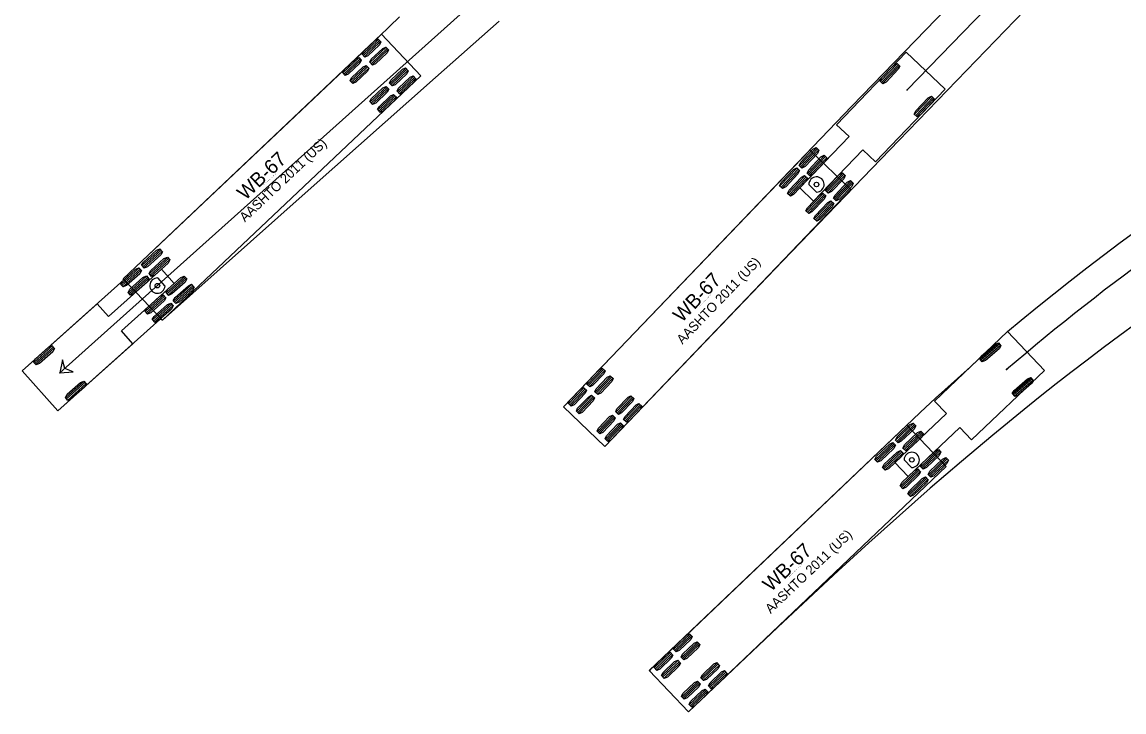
# Model space of a CAD drawing. Extents: x 2175591 to 2194071, y 76570 to 86955.
# Drawn here: x 2176278.8 to 2176443, y 77091.2 to 77193.9 of the extents above; entities that cross this region are included whole.
import ezdxf

# ---------------------------------------------------------------- set-up
doc = ezdxf.new("R2010")
doc.units = 0
doc.layers.add('C-UTIL-STRM-TEXT', color=7, linetype='Continuous')

msp = doc.modelspace()

# ---------------------------------------------------------------- linework, layer by layer
at = {"layer": 'C-UTIL-STRM-TEXT'}
for p, q in [((2176410.68, 77183.82), (2176502.54, 77278.59)), ((2176348.69, 77199.2), (2176284.46, 77141.66)), ((2176332.37, 77192.12), (2176293.88, 77155.69)), ((2176329.52, 77189.11), (2176331.91, 77191.37)), ((2176329.67, 77188.94), (2176332.07, 77191.21)), ((2176329.83, 77188.77), (2176332.23, 77191.04)), ((2176338.22, 77185.95), (2176332.37, 77192.12)), ((2176330.65, 77187.91), (2176333.05, 77190.18)), ((2176330.81, 77187.74), (2176333.21, 77190.01)), ((2176330.97, 77187.57), (2176333.36, 77189.84)), ((2176410.56, 77189.47), (2176400.18, 77178.65)), ((2176416.33, 77183.93), (2176410.56, 77189.47)), ((2176410.56, 77189.47), (2176410.56, 77189.47)), ((2176326.61, 77186.36), (2176329.01, 77188.62)), ((2176326.77, 77186.19), (2176329.17, 77188.46)), ((2176326.93, 77186.02), (2176329.32, 77188.29)), ((2176327.75, 77185.16), (2176330.14, 77187.43)), ((2176327.9, 77184.99), (2176330.3, 77187.26)), ((2176409.23, 77187.75), (2176406.69, 77185.1)), ((2176409.39, 77187.59), (2176406.85, 77184.94)), ((2176409.56, 77187.43), (2176407.02, 77184.79)), ((2176299.73, 77149.52), (2176338.22, 77185.95)), ((2176328.06, 77184.82), (2176330.46, 77187.09)), ((2176333.6, 77184.8), (2176335.99, 77187.06)), ((2176333.75, 77184.63), (2176336.15, 77186.9)), ((2176333.91, 77184.46), (2176336.31, 77186.73)), ((2176334.73, 77183.6), (2176337.13, 77185.87)), ((2176334.89, 77183.43), (2176337.28, 77185.7)), ((2176330.69, 77182.05), (2176333.09, 77184.31)), ((2176330.85, 77181.88), (2176333.24, 77184.15)), ((2176331.01, 77181.71), (2176333.4, 77183.98)), ((2176335.05, 77183.26), (2176337.44, 77185.53)), ((2176331.83, 77180.85), (2176334.22, 77183.12)), ((2176331.98, 77180.68), (2176334.38, 77182.95)), ((2176332.14, 77180.52), (2176334.54, 77182.78)), ((2176405.95, 77173.11), (2176416.33, 77183.93)), ((2176414.34, 77182.84), (2176411.8, 77180.2)), ((2176414.5, 77182.69), (2176411.96, 77180.04)), ((2176414.67, 77182.53), (2176412.13, 77179.88)), ((2176400.18, 77178.65), (2176402.03, 77176.87)), ((2176402.03, 77176.87), (2176394.69, 77169.22)), ((2176396.19, 77174.85), (2176359.5, 77136.61)), ((2176397.18, 77175.19), (2176394.64, 77172.55)), ((2176397.35, 77175.03), (2176394.81, 77172.39)), ((2176397.51, 77174.88), (2176394.97, 77172.23)), ((2176402.32, 77168.97), (2176396.19, 77174.85)), ((2176396.19, 77174.85), (2176396.19, 77174.85)), ((2176396.76, 77167.24), (2176404.1, 77174.89)), ((2176404.1, 77174.89), (2176405.95, 77173.11)), ((2176398.37, 77174.05), (2176395.83, 77171.4)), ((2176398.54, 77173.89), (2176396, 77171.25)), ((2176398.7, 77173.73), (2176396.16, 77171.09)), ((2176394.27, 77172.16), (2176391.73, 77169.52)), ((2176394.44, 77172), (2176391.9, 77169.36)), ((2176394.6, 77171.84), (2176392.06, 77169.2)), ((2176395.46, 77171.02), (2176392.92, 77168.37)), ((2176395.63, 77170.86), (2176393.09, 77168.22)), ((2176401.1, 77171.43), (2176398.56, 77168.79)), ((2176401.27, 77171.27), (2176398.73, 77168.63)), ((2176401.43, 77171.11), (2176398.89, 77168.47)), ((2176395.79, 77170.7), (2176393.25, 77168.06)), ((2176394.69, 77169.22), (2176396.76, 77167.24)), ((2176396.04, 77169.72), (2176397.2, 77168.6)), ((2176402.29, 77170.29), (2176399.75, 77167.64)), ((2176402.46, 77170.13), (2176399.92, 77167.48)), ((2176402.62, 77169.97), (2176400.08, 77167.33)), ((2176365.63, 77130.72), (2176402.32, 77168.97)), ((2176398.19, 77168.4), (2176395.65, 77165.75)), ((2176398.36, 77168.24), (2176395.82, 77165.6)), ((2176398.52, 77168.08), (2176395.99, 77165.44)), ((2176399.38, 77167.26), (2176396.84, 77164.61)), ((2176399.55, 77167.1), (2176397.01, 77164.45)), ((2176399.71, 77166.94), (2176397.18, 77164.29)), ((2176296.67, 77157.65), (2176299.4, 77160.1)), ((2176296.82, 77157.48), (2176299.55, 77159.93)), ((2176296.97, 77157.31), (2176299.7, 77159.76)), ((2176297.77, 77156.42), (2176300.5, 77158.87)), ((2176297.92, 77156.25), (2176300.65, 77158.7)), ((2176298.07, 77156.08), (2176300.8, 77158.53)), ((2176299.59, 77157.14), (2176291.69, 77150.06)), ((2176293.54, 77154.85), (2176296.27, 77157.3)), ((2176293.69, 77154.68), (2176296.42, 77157.13)), ((2176293.84, 77154.51), (2176296.57, 77156.96)), ((2176294.64, 77153.62), (2176297.37, 77156.07)), ((2176301.5, 77155), (2176299.59, 77157.14)), ((2176300.29, 77153.61), (2176303.02, 77156.05)), ((2176293.61, 77147.93), (2176301.5, 77155)), ((2176293.88, 77155.69), (2176299.73, 77149.52)), ((2176294.79, 77153.45), (2176297.52, 77155.9)), ((2176294.94, 77153.28), (2176297.67, 77155.73)), ((2176300.12, 77154.6), (2176299.05, 77155.81)), ((2176300.44, 77153.44), (2176303.17, 77155.88)), ((2176300.6, 77153.26), (2176303.33, 77155.71)), ((2176301.39, 77152.38), (2176304.12, 77154.82)), ((2176301.54, 77152.21), (2176304.28, 77154.65)), ((2176301.7, 77152.04), (2176304.43, 77154.48)), ((2176297.16, 77150.8), (2176299.89, 77153.25)), ((2176297.31, 77150.63), (2176300.05, 77153.08)), ((2176297.47, 77150.46), (2176300.2, 77152.91)), ((2176289.98, 77151.97), (2176278.81, 77141.97)), ((2176291.69, 77150.06), (2176289.98, 77151.97)), ((2176298.26, 77149.57), (2176300.99, 77152.02)), ((2176298.42, 77149.4), (2176301.15, 77151.85)), ((2176298.57, 77149.23), (2176301.3, 77151.68)), ((2176299.73, 77149.52), (2176299.73, 77149.52)), ((2176295.32, 77146.02), (2176293.61, 77147.93)), ((2176425.64, 77147.82), (2176414.78, 77137.47)), ((2176431.16, 77142.02), (2176425.64, 77147.82)), ((2176425.64, 77147.82), (2176425.64, 77147.82)), ((2176280.58, 77143.24), (2176283.31, 77145.69)), ((2176280.73, 77143.07), (2176283.46, 77145.52)), ((2176280.88, 77142.9), (2176283.61, 77145.35)), ((2176284.15, 77136.01), (2176295.32, 77146.02)), ((2176424.32, 77146.11), (2176421.53, 77143.72)), ((2176424.47, 77145.93), (2176421.68, 77143.55)), ((2176424.62, 77145.76), (2176421.83, 77143.38)), ((2176278.81, 77141.97), (2176284.15, 77136.01)), ((2176365.3, 77142.33), (2176363.02, 77139.95)), ((2176365.47, 77142.17), (2176363.18, 77139.79)), ((2176365.63, 77142.01), (2176363.35, 77139.63)), ((2176420.29, 77131.68), (2176431.16, 77142.02)), ((2176285.3, 77137.97), (2176288.03, 77140.41)), ((2176285.45, 77137.79), (2176288.19, 77140.24)), ((2176285.61, 77137.62), (2176288.34, 77140.07)), ((2176366.49, 77141.19), (2176364.21, 77138.8)), ((2176366.66, 77141.03), (2176364.37, 77138.65)), ((2176366.82, 77140.87), (2176364.54, 77138.49)), ((2176429.17, 77140.94), (2176426.38, 77138.56)), ((2176429.32, 77140.77), (2176426.53, 77138.39)), ((2176429.47, 77140.59), (2176426.68, 77138.21)), ((2176362.53, 77139.44), (2176360.25, 77137.06)), ((2176362.7, 77139.28), (2176360.41, 77136.9)), ((2176362.86, 77139.12), (2176360.58, 77136.74)), ((2176363.72, 77138.3), (2176361.44, 77135.92)), ((2176363.89, 77138.14), (2176361.61, 77135.76)), ((2176364.06, 77137.98), (2176361.77, 77135.6)), ((2176369.58, 77138.22), (2176367.3, 77135.84)), ((2176369.75, 77138.06), (2176367.47, 77135.68)), ((2176359.5, 77136.61), (2176365.63, 77130.72)), ((2176369.92, 77137.9), (2176367.63, 77135.52)), ((2176370.78, 77137.08), (2176368.49, 77134.7)), ((2176370.94, 77136.92), (2176368.66, 77134.54)), ((2176371.11, 77136.76), (2176368.82, 77134.38)), ((2176414.78, 77137.47), (2176416.55, 77135.61)), ((2176284.15, 77136.01), (2176284.15, 77136.01)), ((2176366.82, 77135.33), (2176364.53, 77132.95)), ((2176366.98, 77135.18), (2176364.7, 77132.79)), ((2176367.15, 77135.02), (2176364.86, 77132.64)), ((2176416.55, 77135.61), (2176408.87, 77128.3)), ((2176368.01, 77134.19), (2176365.72, 77131.81)), ((2176368.17, 77134.03), (2176365.89, 77131.65)), ((2176368.34, 77133.87), (2176366.05, 77131.49)), ((2176410.62, 77133.86), (2176372.24, 77097.31)), ((2176411.63, 77134.16), (2176408.97, 77131.63)), ((2176411.79, 77133.99), (2176409.13, 77131.46)), ((2176411.94, 77133.82), (2176409.29, 77131.29)), ((2176416.48, 77127.7), (2176410.62, 77133.86)), ((2176410.62, 77133.86), (2176410.62, 77133.86)), ((2176410.85, 77126.23), (2176418.52, 77133.54)), ((2176418.52, 77133.54), (2176420.29, 77131.68)), ((2176412.77, 77132.96), (2176410.11, 77130.43)), ((2176412.92, 77132.79), (2176410.27, 77130.27)), ((2176413.08, 77132.63), (2176410.43, 77130.1)), ((2176408.59, 77131.26), (2176405.93, 77128.73)), ((2176408.74, 77131.09), (2176406.09, 77128.56)), ((2176408.9, 77130.93), (2176406.25, 77128.4)), ((2176409.72, 77130.06), (2176407.07, 77127.54)), ((2176409.88, 77129.9), (2176407.23, 77127.37)), ((2176415.37, 77130.22), (2176412.72, 77127.69)), ((2176415.53, 77130.05), (2176412.88, 77127.53)), ((2176415.69, 77129.89), (2176413.04, 77127.36)), ((2176410.04, 77129.73), (2176407.38, 77127.2)), ((2176408.87, 77128.3), (2176410.85, 77126.23)), ((2176410.24, 77128.74), (2176411.35, 77127.57)), ((2176416.51, 77129.03), (2176413.86, 77126.5)), ((2176416.67, 77128.86), (2176414.02, 77126.33)), ((2176416.83, 77128.69), (2176414.17, 77126.17)), ((2176378.1, 77091.15), (2176416.48, 77127.7)), ((2176412.33, 77127.32), (2176409.68, 77124.8)), ((2176412.49, 77127.16), (2176409.84, 77124.63)), ((2176412.65, 77126.99), (2176409.99, 77124.46)), ((2176413.47, 77126.13), (2176410.82, 77123.6)), ((2176413.63, 77125.96), (2176410.97, 77123.43)), ((2176413.79, 77125.8), (2176411.13, 77123.27)), ((2176378.3, 77102.76), (2176375.91, 77100.49)), ((2176378.46, 77102.6), (2176376.07, 77100.32)), ((2176378.62, 77102.43), (2176376.23, 77100.15)), ((2176379.44, 77101.57), (2176377.05, 77099.29)), ((2176379.6, 77101.4), (2176377.21, 77099.13)), ((2176379.75, 77101.24), (2176377.37, 77098.96)), ((2176375.4, 77100), (2176373.01, 77097.73)), ((2176375.56, 77099.84), (2176373.17, 77097.56)), ((2176375.72, 77099.67), (2176373.33, 77097.4)), ((2176376.54, 77098.81), (2176374.15, 77096.53)), ((2176376.7, 77098.64), (2176374.31, 77096.37)), ((2176372.24, 77097.31), (2176378.1, 77091.15)), ((2176376.86, 77098.48), (2176374.47, 77096.2)), ((2176382.39, 77098.47), (2176380, 77096.19)), ((2176382.55, 77098.3), (2176380.16, 77096.02)), ((2176382.71, 77098.13), (2176380.32, 77095.86)), ((2176383.53, 77097.27), (2176381.14, 77094.99)), ((2176383.69, 77097.1), (2176381.3, 77094.83)), ((2176383.85, 77096.94), (2176381.46, 77094.66)), ((2176379.5, 77095.71), (2176377.11, 77093.43)), ((2176379.65, 77095.54), (2176377.26, 77093.27)), ((2176379.81, 77095.37), (2176377.42, 77093.1)), ((2176380.63, 77094.51), (2176378.24, 77092.24)), ((2176380.79, 77094.35), (2176378.4, 77092.07)), ((2176380.95, 77094.18), (2176378.56, 77091.9))]:
    msp.add_line(p, q, dxfattribs=at)
for points in [[(2176508.36, 77278.86), (2176502.22, 77272.5), (2176500.11, 77270.16), (2176497.97, 77267.84), (2176495.95, 77265.7), (2176426.72, 77194.16), (2176409.45, 77176.28), (2176392.19, 77158.38), (2176365.63, 77130.72), (2176359.5, 77136.61), (2176359.7, 77136.82), (2176359.7, 77136.82)], [(2176359.7, 77136.82), (2176402.47, 77181.39), (2176419.75, 77199.27), (2176462.92, 77243.83), (2176467.17, 77248.29), (2176471.25, 77252.61), (2176473.34, 77254.87), (2176475.42, 77257.13), (2176477.47, 77259.4), (2176479.48, 77261.68), (2176481.38, 77263.88), (2176483.31, 77266.17), (2176485.19, 77268.47), (2176487.04, 77270.81), (2176488.74, 77273.02)], [(2176349.89, 77194.08), (2176340.39, 77185.68), (2176321.43, 77168.86), (2176299.73, 77149.52), (2176299.34, 77149.62), (2176284.15, 77136.01), (2176278.81, 77141.97), (2176293.96, 77155.54), (2176293.88, 77155.69), (2176330.52, 77190.37), (2176335.07, 77194.7)], [(2176372.43, 77097.49), (2176408.4, 77131.74), (2176412.64, 77135.77), (2176414.93, 77137.89), (2176417.23, 77139.99), (2176420.11, 77142.56), (2176425.64, 77147.82), (2176427.69, 77149.52), (2176430.11, 77151.5), (2176432.54, 77153.45), (2176434.99, 77155.39), (2176437.46, 77157.3), (2176439.95, 77159.2), (2176442.45, 77161.08), (2176444.97, 77162.93)], [(2176444.81, 77149.03), (2176442.36, 77147.24), (2176439.92, 77145.42), (2176437.5, 77143.59), (2176435.09, 77141.73), (2176432.91, 77140.03), (2176430.52, 77138.14), (2176428.15, 77136.23), (2176423.46, 77132.39), (2176418.78, 77128.46), (2176414.14, 77124.47), (2176409.54, 77120.42), (2176404.97, 77116.33), (2176400.43, 77112.19), (2176395.92, 77108.02), (2176391.43, 77103.81), (2176378.1, 77091.15), (2176372.24, 77097.31), (2176372.43, 77097.49), (2176372.43, 77097.49)]]:
    msp.add_lwpolyline(points, dxfattribs=at)
for points in [[(2176329.87, 77188.73), (2176329.48, 77189.15), (2176329.7, 77189.59), (2176331.42, 77191.22), (2176331.87, 77191.41), (2176332.27, 77191), (2176332.05, 77190.56), (2176330.33, 77188.92)], [(2176331.01, 77187.53), (2176330.61, 77187.95), (2176330.83, 77188.39), (2176332.55, 77190.02), (2176333.01, 77190.22), (2176333.4, 77189.8), (2176333.19, 77189.36), (2176331.46, 77187.73)], [(2176326.97, 77185.98), (2176326.57, 77186.4), (2176326.79, 77186.84), (2176328.52, 77188.47), (2176328.97, 77188.67), (2176329.36, 77188.25), (2176329.15, 77187.81), (2176327.42, 77186.17)], [(2176328.1, 77184.78), (2176327.71, 77185.2), (2176327.92, 77185.64), (2176329.65, 77187.27), (2176330.1, 77187.47), (2176330.5, 77187.05), (2176330.28, 77186.61), (2176328.55, 77184.98)], [(2176409.18, 77187.79), (2176409.6, 77187.39), (2176409.37, 77186.9), (2176407.54, 77185), (2176407.06, 77184.75), (2176406.65, 77185.14), (2176406.88, 77185.63), (2176408.71, 77187.54)], [(2176333.95, 77184.42), (2176333.56, 77184.84), (2176333.77, 77185.28), (2176335.5, 77186.91), (2176335.95, 77187.11), (2176336.35, 77186.69), (2176336.13, 77186.25), (2176334.4, 77184.61)], [(2176335.08, 77183.22), (2176334.69, 77183.64), (2176334.91, 77184.08), (2176336.63, 77185.72), (2176337.09, 77185.91), (2176337.48, 77185.49), (2176337.26, 77185.05), (2176335.54, 77183.42)], [(2176331.04, 77181.67), (2176330.65, 77182.09), (2176330.87, 77182.53), (2176332.59, 77184.16), (2176333.05, 77184.36), (2176333.44, 77183.94), (2176333.22, 77183.5), (2176331.5, 77181.86)], [(2176332.18, 77180.47), (2176331.79, 77180.89), (2176332, 77181.33), (2176333.73, 77182.97), (2176334.18, 77183.16), (2176334.58, 77182.74), (2176334.36, 77182.3), (2176332.63, 77180.67)], [(2176414.3, 77182.88), (2176414.71, 77182.49), (2176414.48, 77182), (2176412.65, 77180.09), (2176412.17, 77179.84), (2176411.76, 77180.24), (2176411.99, 77180.73), (2176413.82, 77182.63)], [(2176397.14, 77175.23), (2176397.55, 77174.84), (2176397.32, 77174.35), (2176395.49, 77172.44), (2176395.01, 77172.19), (2176394.6, 77172.59), (2176394.83, 77173.08), (2176396.66, 77174.98)], [(2176398.33, 77174.09), (2176398.74, 77173.69), (2176398.51, 77173.2), (2176396.68, 77171.3), (2176396.2, 77171.05), (2176395.79, 77171.44), (2176396.02, 77171.93), (2176397.85, 77173.84)], [(2176394.23, 77172.2), (2176394.64, 77171.81), (2176394.41, 77171.32), (2176392.59, 77169.41), (2176392.11, 77169.16), (2176391.69, 77169.56), (2176391.92, 77170.05), (2176393.75, 77171.95)], [(2176395.42, 77171.06), (2176395.83, 77170.66), (2176395.6, 77170.17), (2176393.78, 77168.27), (2176393.3, 77168.02), (2176392.88, 77168.41), (2176393.11, 77168.9), (2176394.94, 77170.81)], [(2176401.06, 77171.47), (2176401.47, 77171.07), (2176401.24, 77170.58), (2176399.41, 77168.68), (2176398.93, 77168.43), (2176398.52, 77168.82), (2176398.75, 77169.31), (2176400.58, 77171.22)], [(2176402.25, 77170.33), (2176402.66, 77169.93), (2176402.43, 77169.44), (2176400.6, 77167.54), (2176400.12, 77167.29), (2176399.71, 77167.68), (2176399.94, 77168.17), (2176401.77, 77170.08)], [(2176398.15, 77168.44), (2176398.56, 77168.04), (2176398.33, 77167.55), (2176396.51, 77165.65), (2176396.03, 77165.4), (2176395.61, 77165.79), (2176395.84, 77166.28), (2176397.67, 77168.19)], [(2176399.34, 77167.3), (2176399.76, 77166.9), (2176399.52, 77166.41), (2176397.7, 77164.51), (2176397.22, 77164.26), (2176396.8, 77164.65), (2176397.03, 77165.14), (2176398.86, 77167.05)], [(2176297.01, 77157.27), (2176296.63, 77157.7), (2176296.89, 77158.17), (2176298.86, 77159.93), (2176299.36, 77160.14), (2176299.74, 77159.72), (2176299.47, 77159.25), (2176297.51, 77157.48)], [(2176298.11, 77156.04), (2176297.73, 77156.47), (2176298, 77156.94), (2176299.96, 77158.7), (2176300.46, 77158.91), (2176300.84, 77158.49), (2176300.57, 77158.02), (2176298.61, 77156.25)], [(2176293.88, 77154.47), (2176293.5, 77154.89), (2176293.77, 77155.36), (2176295.73, 77157.13), (2176296.23, 77157.34), (2176296.61, 77156.91), (2176296.34, 77156.44), (2176294.38, 77154.68)], [(2176294.98, 77153.24), (2176294.6, 77153.66), (2176294.87, 77154.14), (2176296.83, 77155.9), (2176297.33, 77156.11), (2176297.71, 77155.68), (2176297.45, 77155.21), (2176295.48, 77153.45)], [(2176300.63, 77153.22), (2176300.25, 77153.65), (2176300.52, 77154.12), (2176302.49, 77155.88), (2176302.98, 77156.09), (2176303.37, 77155.67), (2176303.1, 77155.2), (2176301.13, 77153.44)], [(2176301.73, 77151.99), (2176301.35, 77152.42), (2176301.62, 77152.89), (2176303.59, 77154.65), (2176304.08, 77154.87), (2176304.47, 77154.44), (2176304.2, 77153.97), (2176302.23, 77152.21)], [(2176297.51, 77150.42), (2176297.12, 77150.85), (2176297.39, 77151.32), (2176299.36, 77153.08), (2176299.86, 77153.29), (2176300.24, 77152.87), (2176299.97, 77152.4), (2176298, 77150.63)], [(2176298.61, 77149.19), (2176298.22, 77149.62), (2176298.49, 77150.09), (2176300.46, 77151.85), (2176300.96, 77152.06), (2176301.34, 77151.64), (2176301.07, 77151.17), (2176299.1, 77149.41)], [(2176280.92, 77142.86), (2176280.54, 77143.28), (2176280.81, 77143.75), (2176282.77, 77145.52), (2176283.27, 77145.73), (2176283.65, 77145.3), (2176283.38, 77144.83), (2176281.42, 77143.07)], [(2176424.28, 77146.15), (2176424.66, 77145.72), (2176424.38, 77145.25), (2176422.37, 77143.53), (2176421.87, 77143.33), (2176421.5, 77143.77), (2176421.78, 77144.23), (2176423.78, 77145.95)], [(2176284.46, 77141.66), (2176286.45, 77141.81), (2176285.2, 77142.32), (2176284.83, 77143.62)], [(2176365.26, 77142.37), (2176365.68, 77141.97), (2176365.48, 77141.52), (2176363.83, 77139.8), (2176363.39, 77139.59), (2176362.98, 77139.99), (2176363.17, 77140.44), (2176364.82, 77142.15)], [(2176285.65, 77137.58), (2176285.26, 77138.01), (2176285.53, 77138.48), (2176287.5, 77140.24), (2176288, 77140.45), (2176288.38, 77140.03), (2176288.11, 77139.56), (2176286.14, 77137.8)], [(2176366.45, 77141.23), (2176366.87, 77140.83), (2176366.67, 77140.38), (2176365.03, 77138.66), (2176364.58, 77138.45), (2176364.17, 77138.84), (2176364.36, 77139.3), (2176366.01, 77141.01)], [(2176429.13, 77140.99), (2176429.5, 77140.55), (2176429.23, 77140.09), (2176427.22, 77138.37), (2176426.72, 77138.17), (2176426.34, 77138.61), (2176426.62, 77139.07), (2176428.63, 77140.78)], [(2176362.49, 77139.48), (2176362.91, 77139.09), (2176362.71, 77138.63), (2176361.07, 77136.92), (2176360.62, 77136.7), (2176360.21, 77137.1), (2176360.4, 77137.55), (2176362.05, 77139.27)], [(2176363.68, 77138.34), (2176364.1, 77137.94), (2176363.9, 77137.49), (2176362.26, 77135.78), (2176361.81, 77135.56), (2176361.4, 77135.96), (2176361.59, 77136.41), (2176363.24, 77138.12)], [(2176369.54, 77138.26), (2176369.96, 77137.86), (2176369.76, 77137.41), (2176368.12, 77135.7), (2176367.67, 77135.48), (2176367.26, 77135.88), (2176367.45, 77136.33), (2176369.1, 77138.05)], [(2176370.73, 77137.12), (2176371.15, 77136.72), (2176370.95, 77136.27), (2176369.31, 77134.55), (2176368.86, 77134.34), (2176368.45, 77134.74), (2176368.65, 77135.19), (2176370.29, 77136.9)], [(2176366.77, 77135.37), (2176367.19, 77134.98), (2176366.99, 77134.52), (2176365.35, 77132.81), (2176364.9, 77132.6), (2176364.49, 77132.99), (2176364.69, 77133.44), (2176366.33, 77135.16)], [(2176367.97, 77134.23), (2176368.38, 77133.84), (2176368.18, 77133.38), (2176366.54, 77131.67), (2176366.09, 77131.45), (2176365.68, 77131.85), (2176365.88, 77132.3), (2176367.52, 77134.02)], [(2176411.59, 77134.2), (2176411.98, 77133.78), (2176411.73, 77133.3), (2176409.82, 77131.48), (2176409.33, 77131.25), (2176408.93, 77131.67), (2176409.19, 77132.15), (2176411.1, 77133.97)], [(2176412.73, 77133), (2176413.12, 77132.59), (2176412.87, 77132.11), (2176410.96, 77130.29), (2176410.47, 77130.06), (2176410.07, 77130.47), (2176410.32, 77130.95), (2176412.24, 77132.77)], [(2176408.55, 77131.3), (2176408.94, 77130.89), (2176408.69, 77130.41), (2176406.78, 77128.59), (2176406.29, 77128.36), (2176405.89, 77128.77), (2176406.14, 77129.25), (2176408.06, 77131.07)], [(2176409.68, 77130.1), (2176410.08, 77129.69), (2176409.83, 77129.21), (2176407.91, 77127.39), (2176407.42, 77127.16), (2176407.03, 77127.58), (2176407.28, 77128.06), (2176409.19, 77129.88)], [(2176415.34, 77130.26), (2176415.73, 77129.85), (2176415.48, 77129.37), (2176413.57, 77127.55), (2176413.07, 77127.32), (2176412.68, 77127.73), (2176412.93, 77128.21), (2176414.84, 77130.03)], [(2176416.47, 77129.07), (2176416.87, 77128.65), (2176416.61, 77128.17), (2176414.7, 77126.35), (2176414.21, 77126.12), (2176413.82, 77126.54), (2176414.07, 77127.02), (2176415.98, 77128.84)], [(2176412.29, 77127.37), (2176412.69, 77126.95), (2176412.44, 77126.47), (2176410.52, 77124.65), (2176410.03, 77124.42), (2176409.64, 77124.84), (2176409.89, 77125.32), (2176411.8, 77127.14)], [(2176413.43, 77126.17), (2176413.83, 77125.76), (2176413.57, 77125.28), (2176411.66, 77123.46), (2176411.17, 77123.23), (2176410.78, 77123.64), (2176411.03, 77124.12), (2176412.94, 77125.94)], [(2176378.26, 77102.8), (2176378.66, 77102.39), (2176378.44, 77101.95), (2176376.72, 77100.31), (2176376.27, 77100.11), (2176375.87, 77100.53), (2176376.09, 77100.97), (2176377.81, 77102.61)], [(2176379.4, 77101.61), (2176379.79, 77101.19), (2176379.58, 77100.75), (2176377.86, 77099.11), (2176377.4, 77098.92), (2176377.01, 77099.33), (2176377.23, 77099.78), (2176378.95, 77101.41)], [(2176375.37, 77100.04), (2176375.76, 77099.63), (2176375.54, 77099.19), (2176373.82, 77097.55), (2176373.37, 77097.35), (2176372.98, 77097.77), (2176373.19, 77098.21), (2176374.91, 77099.85)], [(2176376.5, 77098.85), (2176376.9, 77098.44), (2176376.68, 77097.99), (2176374.96, 77096.35), (2176374.51, 77096.16), (2176374.11, 77096.57), (2176374.33, 77097.02), (2176376.05, 77098.66)], [(2176382.35, 77098.51), (2176382.75, 77098.09), (2176382.53, 77097.65), (2176380.81, 77096.01), (2176380.36, 77095.82), (2176379.96, 77096.23), (2176380.18, 77096.67), (2176381.9, 77098.31)], [(2176383.49, 77097.31), (2176383.89, 77096.9), (2176383.67, 77096.45), (2176381.95, 77094.82), (2176381.5, 77094.62), (2176381.1, 77095.04), (2176381.32, 77095.48), (2176383.04, 77097.12)], [(2176379.46, 77095.75), (2176379.85, 77095.33), (2176379.64, 77094.89), (2176377.92, 77093.25), (2176377.46, 77093.06), (2176377.07, 77093.47), (2176377.28, 77093.92), (2176379, 77095.55)], [(2176380.59, 77094.55), (2176380.99, 77094.14), (2176380.77, 77093.7), (2176379.05, 77092.06), (2176378.6, 77091.86), (2176378.21, 77092.28), (2176378.42, 77092.72), (2176380.14, 77094.36)]]:
    msp.add_lwpolyline(points, close=True, dxfattribs=at)
for centre, radius in [((2176410.68, 77183.82), 0.0417), ((2176397.18, 77169.74), 0.34), ((2176298.98, 77154.67), 0.34), ((2176284.46, 77141.66), 0.0417), ((2176425.5, 77142.16), 0.0417), ((2176411.38, 77128.71), 0.34)]:
    msp.add_circle(centre, radius, dxfattribs=at)
for centre, radius, start, end in [((2176661.3, 76866.29), 362.91, 121.0491, 130.5216), ((2176397.18, 77169.74), 1.14, 271.1873, 181.1873), ((2176298.98, 77154.67), 1.14, 86.851, 356.851), ((2176411.38, 77128.71), 1.14, 268.6017, 178.6017)]:
    msp.add_arc(centre, radius, start, end, dxfattribs=at)

# ---------------------------------------------------------------- texts
for s, height, rotation, p in [('AASHTO 2011 (US)', 1.4167, 43.4268, (2176312.02, 77164.07)), ('WB-67', 2.125, 43.4268, (2176312.07, 77167.29)), ('(c) 2019 Transoft Solutions, Inc. All rights reserved.', 0.085, 43.4268, (2176314.82, 77169.6)), ('AASHTO 2011 (US)', 1.4167, 46.1873, (2176377.21, 77145.85)), ('WB-67', 2.125, 46.1873, (2176377.11, 77149.07)), ('(c) 2019 Transoft Solutions, Inc. All rights reserved.', 0.085, 46.1873, (2176379.74, 77151.51)), ('AASHTO 2011 (US)', 1.4167, 43.6017, (2176390.35, 77105.74)), ('WB-67', 2.125, 43.6017, (2176390.4, 77108.96)), ('(c) 2019 Transoft Solutions, Inc. All rights reserved.', 0.085, 43.6017, (2176393.14, 77111.28))]:
    msp.add_text(s, height=height, rotation=rotation, dxfattribs=at).set_placement(p)

doc.saveas('drawing.dxf')
